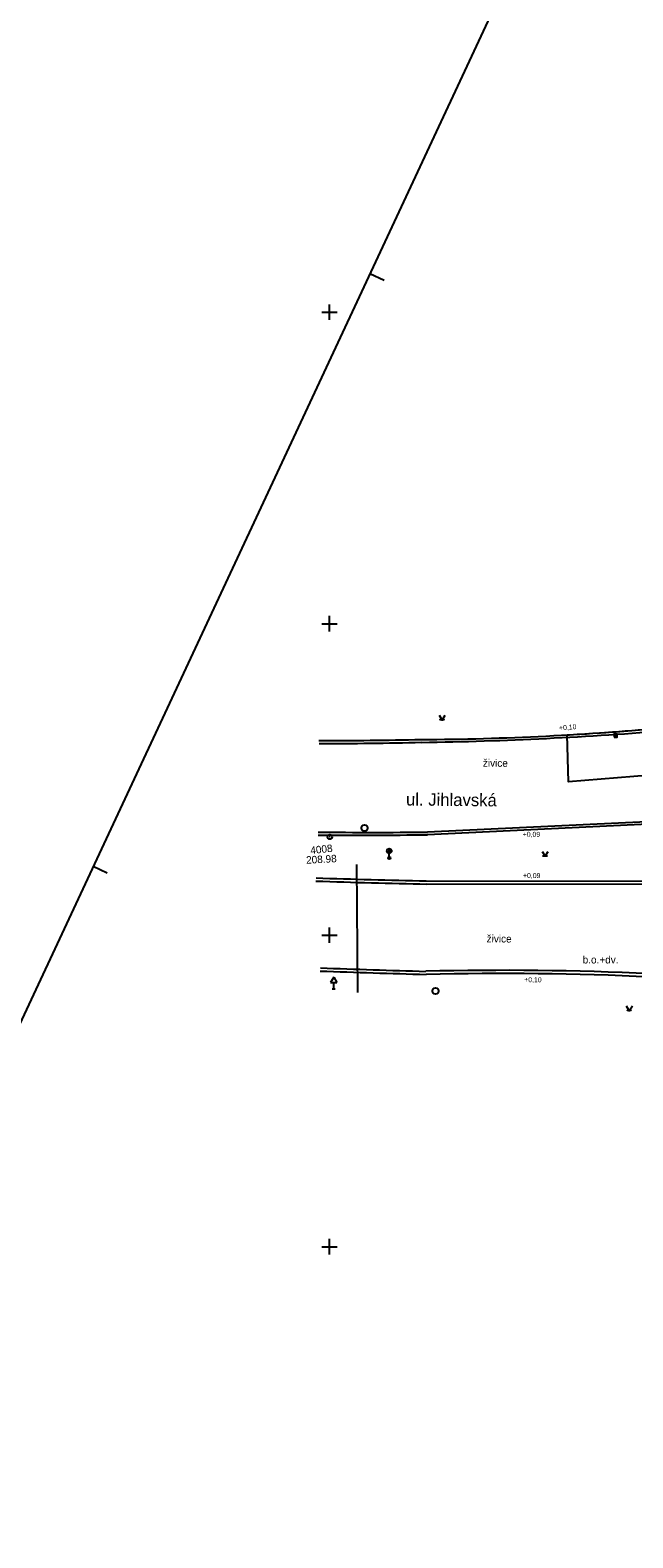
# Model space of a CAD drawing. Extents: x -599151 to -598424, y -1163476 to -1161924.
# Drawn here: x -599024 to -598975.7, y -1163223.4 to -1163102.4 of the extents above; entities that cross this region are included whole.
import ezdxf

# ---------------------------------------------------------------- set-up
doc = ezdxf.new("R2010")
doc.units = 0
for name, color, linetype in [('Vrstva 1', 7, 'Continuous'), ('Vrstva 14', 7, 'Continuous'), ('Vrstva 19', 7, 'Continuous'), ('Vrstva 2', 7, 'Continuous'), ('Vrstva 25', 7, 'Continuous'), ('Vrstva 29', 7, 'Continuous'), ('Vrstva 42', 7, 'Continuous'), ('Vrstva 44', 7, 'Continuous'), ('Vrstva 49', 7, 'Continuous'), ('Vrstva 50', 7, 'Continuous'), ('Vrstva 62', 7, 'Continuous'), ('Vrstva 63', 7, 'Continuous'), ('Vrstva 7', 7, 'Continuous')]:
    doc.layers.add(name, color=color, linetype=linetype)

msp = doc.modelspace()

# ---------------------------------------------------------------- linework, layer by layer
at = {"layer": 'Vrstva 1'}
for p, q in [((-598952.34, -1163026.78), (-599107.83, -1163359.76)), ((-598995.63, -1163122.45), (-598996.77, -1163121.92)), ((-599017.85, -1163170.02), (-599018.98, -1163169.49))]:
    msp.add_line(p, q, dxfattribs=at)
at = {"layer": 'Vrstva 14'}
for points in [[(-598991.22, -1163157.35), (-598990.97, -1163157.73), (-598990.72, -1163157.35)], [(-598982.95, -1163168.29), (-598982.7, -1163168.66), (-598982.45, -1163168.29)], [(-598976.2, -1163180.68), (-598975.95, -1163181.06), (-598975.7, -1163180.68)]]:
    msp.add_lwpolyline(points, dxfattribs=at)
for centre in [(-598991.1, -1163157.7), (-598990.85, -1163157.7), (-598982.83, -1163168.64), (-598982.58, -1163168.64), (-598976.08, -1163181.03), (-598975.83, -1163181.03)]:
    msp.add_circle(centre, 0.025, dxfattribs=at)
at = {"layer": 'Vrstva 19'}
for p, q in [((-598999.67, -1163178.37), (-598999.92, -1163178.8)), ((-598999.92, -1163178.8), (-598999.42, -1163178.8)), ((-598999.67, -1163178.37), (-598999.42, -1163178.8)), ((-598999.67, -1163179.3), (-598999.67, -1163178.8)), ((-598999.8, -1163179.3), (-598999.55, -1163179.3))]:
    msp.add_line(p, q, dxfattribs=at)
at = {"layer": 'Vrstva 2'}
for radius in [0.187, 0.00896]:
    msp.add_circle((-598999.98, -1163167.11), radius, dxfattribs=at)
at = {"layer": 'Vrstva 25'}
msp.add_line((-598977.18, -1163159), (-598976.93, -1163158.98), dxfattribs=at)
msp.add_lwpolyline([(-598977.17, -1163159.12), (-598976.92, -1163159.11), (-598976.93, -1163158.86), (-598977.18, -1163158.87)], close=True, dxfattribs=at)
for centre in [(-598997.2, -1163166.39), (-598991.5, -1163179.48)]:
    msp.add_circle(centre, 0.25, dxfattribs=at)
at = {"layer": 'Vrstva 29'}
for p, q in [((-598995.34, -1163168.37), (-598995.08, -1163168.1)), ((-598995.07, -1163168.37), (-598995.34, -1163168.1)), ((-598995.21, -1163168.7), (-598995.21, -1163168.43))]:
    msp.add_line(p, q, dxfattribs=at)
for centre, radius in [((-598995.21, -1163168.24), 0.188), ((-598995.21, -1163168.8), 0.1)]:
    msp.add_circle(centre, radius, dxfattribs=at)
at = {"layer": 'Vrstva 44'}
msp.add_line((-598997.83, -1163169.32), (-598997.77, -1163179.59), dxfattribs=at)
at = {"layer": 'Vrstva 62'}
for p, q in [((-599000, -1163125.62), (-599000, -1163124.38)), ((-599000.62, -1163125), (-598999.38, -1163125)), ((-599000.62, -1163150), (-598999.38, -1163150)), ((-599000, -1163150.62), (-599000, -1163149.38)), ((-599000.62, -1163175), (-598999.38, -1163175)), ((-599000, -1163175.62), (-599000, -1163174.38)), ((-599000, -1163200.62), (-599000, -1163199.38)), ((-599000.62, -1163200), (-598999.38, -1163200))]:
    msp.add_line(p, q, dxfattribs=at)
at = {"layer": 'Vrstva 63'}
msp.add_lwpolyline([(-598959.35, -1163164.18), (-598968.36, -1163165.51), (-598969.03, -1163161.72), (-598980.83, -1163162.69), (-598980.94, -1163158.92)], dxfattribs=at)
msp.add_arc((-598993.98, -1162931.86), 227.44, 273.2856, 275.3852, dxfattribs=at)
at = {"layer": 'Vrstva 7'}
msp.add_line((-598992.19, -1163170.89), (-598972.9, -1163170.91), dxfattribs=at)
for points in [[(-598956.94, -1163163.62), (-598968.39, -1163165.31), (-598972.27, -1163165.79), (-598992.15, -1163166.72)], [(-598959.35, -1163164.18), (-598968.36, -1163165.51), (-598972.25, -1163165.99), (-598992.14, -1163166.94)], [(-598992.24, -1163170.64), (-598972.88, -1163170.67)]]:
    msp.add_lwpolyline(points, dxfattribs=at)
for centre, radius, start, end in [((-598993.98, -1162931.86), 227.44, 270.3339, 275.3852), ((-599000.35, -1162833.12), 326.26, 269.9119, 271.3521), ((-599000.77, -1162833.12), 326.5, 269.9859, 271.4326), ((-598997.07, -1162866.61), 292.95, 270.8728, 274.792), ((-598997.71, -1162827.03), 339.95, 269.4599, 270.938), ((-598996.55, -1162827.01), 339.74, 269.265, 270.7415), ((-598981.73, -1162619.42), 551.32, 267.9882, 268.9072), ((-598981.79, -1162619.42), 551.57, 267.9945, 268.9193), ((-598938.34, -1161355.07), 1823.63, 268.03933, 268.3047), ((-598985.97, -1163430.07), 252.25, 83.2488, 91.4348), ((-598938.62, -1161355.06), 1823.88, 268.04806, 268.3149), ((-598986.23, -1163440.36), 262.28, 83.4556, 91.3146)]:
    msp.add_arc(centre, radius, start, end, dxfattribs=at)

# ---------------------------------------------------------------- texts
at = {"layer": 'Vrstva 2'}
for s, rotation, p in [('4008', 6.3437, (-599001.51, -1163168.5)), ('208.98', 3.0271, (-599001.87, -1163169.27))]:
    msp.add_text(s, height=0.6, rotation=rotation, dxfattribs=at).set_placement(p)
at = {"layer": 'Vrstva 42'}
msp.add_text('ul. Jihlavská', height=1, rotation=359.403, dxfattribs=at).set_placement((-598993.87, -1163164.59))
at = {"layer": 'Vrstva 49'}
for p in [(-598987.7, -1163161.47), (-598987.4, -1163175.57)]:
    msp.add_text('živice', height=0.6, rotation=359.3724, dxfattribs=at).set_placement(p)
msp.add_text('b.o.+dv.', height=0.6, dxfattribs=at).set_placement((-598979.69, -1163177.27))
at = {"layer": 'Vrstva 50'}
for s, rotation, p in [('+0,10', 4.6297, (-598981.57, -1163158.57)), ('+0,09', 359.6453, (-598984.5, -1163167.1)), ('+0,09', 359.6453, (-598984.48, -1163170.41)), ('+0,10', 359.6453, (-598984.38, -1163178.77))]:
    msp.add_text(s, height=0.4, rotation=rotation, dxfattribs=at).set_placement(p)

doc.saveas('drawing.dxf')
